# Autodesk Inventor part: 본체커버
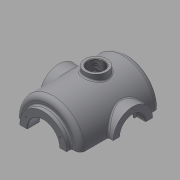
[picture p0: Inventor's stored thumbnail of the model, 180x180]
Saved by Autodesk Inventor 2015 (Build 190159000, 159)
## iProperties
Created: 2016-02
Part Number: 본체커버
Material: 일반
Document SubType Name: Modeling
Designer: mduedu
Density: 1 g/cm^3
Appearance: 기본값
Mass: 438.034 g
Surface Area: 904.884 cm^2
Volume: 438.034 cm^3
Author: mduedu
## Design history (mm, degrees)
sketch "스케치2"
  geometry: L1 (0, 90)-(0, -90); L2 (65, -65.993)-(65, 90); L3 (65, 90)-(0, 90); A1 r 100 centre (0, 10) between (0, -90) and (65, -65.993); 2 further points
  constraints: 6 end point, 2 point on circle, 1 centre point, 1 coincident, 1 horizontal, 1 midpoint, 1 parallel, 1 point on line, 1 vertical
  dimensions: "d3" = 180 distance of L1.start L1.end; "d5" = 130 diameter of L2 L1; "d6" = 100 radius of A1
revolve "회전1" sketch "스케치2" stored, may be unused: angle "d7" = 90 deg
sketch "스케치3"
  geometry: C1 r 47.5 at (0, 0); 1 further point
  constraints: 1 centre point, 1 coincident
  dimensions: "d8" = 95 diameter of C1
extrude "돌출2" join sketch "스케치3" distance "d10" = 10; taper "d11" = 0 deg
sketch "스케치5"
  geometry: L1 (47.5, 100)-(47.5, 90) reference; L2 (47.5, 90)-(65, 90) reference; L3 (65, 90)-(65, -65.993) reference; L4 (-65, -65.993)-(-65, 90) reference; L5 (-65, 90)-(-47.5, 90) reference; L6 (-47.5, 90)-(-47.5, 100) reference; L7 (-47.5, 100)-(47.5, 100) reference; L8 (55, 75)-(55, -61.239); L9 (0, 75)-(55, 75); L10 (0, 75)-(0, -80); A1 r 100 centre (0, 10) between (-65, -65.993) and (0, -90) reference; A2 r 100 centre (0, 10) between (0, -90) and (65, -65.993) reference; A3 r 90 centre (0, 10) between (0, -80) and (55, -61.239); 1 further point
  constraints: 6 end point, 2 point on circle, 1 centre point, 1 parallel, 1 perpendicular, 1 point on line, 1 vertical
  dimensions: "d13" = 10 distance between parallel lines of L3 L8; "d14" = 10 radial gap between concentric circles of A3 A1; "d15" = 15 distance between parallel lines of L9 L2
revolve "회전2" sketch "스케치5" stored, may be unused: angle "d16" = 90 deg
hole "구멍1" diameter "d19" = 65; stored, may be unused: countersink angle "d23" = 90 deg, drill point angle "d25" = 118 deg; dims "d17" = 10, "d18" = 10, "d20" = 6, "d21" = 4, "d22" = 2, "d24" = 8
node "작업 평면1"
sketch "스케치6"
  geometry: L1 (47.5, 100)-(-47.5, 100) reference; C1 r 40 at (0, -7); 1 further point
  constraints: 1 centre point, 1 vertical alignment
  dimensions: "d27" = 80 diameter of C1; "d29" = 107 distance from line of C1.centre L1
extrude "돌출3" join sketch "스케치6" stored distance "d30" = 10; taper "d31" = 0 deg
hole "구멍2" diameter "d34" = 42; stored, may be unused: countersink angle "d38" = 90 deg, drill point angle "d40" = 118 deg; dims "d32" = 10, "d33" = 10, "d35" = 6, "d36" = 52, "d37" = 18, "d39" = 8
sketch "스케치7" dims "d41" = 65
  geometry: C1 r 40 at (0, 0) reference; 3 further points
  constraints: 2 vertical alignment, 1 coincident, 2 other
hole "구멍3" sketch "스케치7" at (0, 32.5) diameter "d43" = 3.242; stored, may be unused: countersink angle "d47" = 90 deg, drill point angle "d49" = 118 deg; dims "d44" = 11, "d45" = 13, "d46" = 18, "d48" = 13
sketch "스케치8" dims "d53" = 80
  geometry: 3 further points
  constraints: 2 vertical alignment, 1 coincident, 2 other
hole "구멍4" sketch "스케치8" at (0, -40) diameter "d56" = 3.242; stored, may be unused: countersink angle "d60" = 90 deg, drill point angle "d62" = 118 deg; dims "d57" = 11, "d58" = 13, "d59" = 18, "d61" = 13
fillet "모깎기1" dims "d66" = 10
fillet "모깎기2" dims "d67" = 3
fillet "모깎기3" dims "d68" = 0.3
chamfer "모따기1" distance "d69" = 1; stored, may be unused: second distance "d70" = 2, angle "d71" = 45 deg
node "작업 평면5"
sketch "스케치10"
  geometry: L1 (-50, 66)-(50, 66); L2 (50, 66)-(50, 50); L3 (50, 50)-(-50, 50); L4 (-50, 50)-(-50, 66); 2 further points
  constraints: 8 end point, 2 horizontal, 2 vertical, 1 midpoint, 1 vertical alignment
  dimensions: "d177" = 50 distance from line of L3 point (0, 0); "d178" = 100 distance of L1.start L1.end; "d179" = 16 distance of L3.end L1.start
extrude "돌출5" join sketch "스케치10" stored distance "d84" = 10; taper "d85" = 0 deg
sketch "스케치21" dims "d180" = 220, "d182" = 130
  geometry: L1 (65, 58)-(-65, 58); L2 (-65, 58)-(-65, -32); L3 (-65, -32)-(65, -32); L4 (65, -32)-(65, 58); L5 (50, 50)-(50, 66) reference; 4 further points
  constraints: 8 end point, 3 horizontal alignment, 3 midpoint, 2 parallel, 1 horizontal, 1 perpendicular, 1 vertical alignment, 4 other
extrude "돌출13" join sketch "스케치21" distance "d183" = 10; taper "d184" = 0 deg
sketch "스케치11"
  geometry: L1 (-65, 80)-(-65, -61.239) reference; L2 (-100, -97)-(-100, -32) reference; L3 (-65, -42.793)-(-100, -63); L4 (-100, -97)-(-110, -97) reference; 1 further point
  constraints: 2 end point, 2 point on line
  dimensions: "d185" = 34 distance from line of L3.end L4; "d186" = 120 deg angle of L2 L3
feature "리브1" sketch "스케치11" dims "d88" = 1, "d89" = 16, "d90" = 0, "d91" = 0, "d92" = 1, "d93" = 1
fillet "모깎기12"
fillet "모깎기13"
fillet "모깎기16" dims "d167" = 3
fillet "모깎기18"
fillet "모깎기17" dims "d168" = 3
fillet "모깎기19" dims "d187" = 3
node "작업 평면6"
sketch "스케치19"
  geometry: L1 (75, -47)-(75, 33) reference; L2 (-75, -47)-(-75, 33) reference; L3 (75, -7)-(-75, -7); C1 r 22.5 at (0, -7); 1 further point
  constraints: 3 midpoint, 2 end point, 1 centre point
  dimensions: "d149" = 45 diameter of C1
extrude "돌출11" join sketch "스케치19" stored distance "d150" = 10; taper "d151" = 0 deg
hole "구멍6" diameter "d154" = 33.376; stored, may be unused: countersink angle "d158" = 90 deg, drill point angle "d160" = 118 deg; dims "d155" = 6, "d156" = 4, "d157" = 2, "d159" = 8, "d190" = 10, "d191" = 10
fillet "모깎기11" dims "d161" = 3
chamfer "모따기3" distance "d164" = 1; stored, may be unused: second distance "d165" = 2, angle "d166" = 45 deg
sketch "스케치22" dims "d189" = 20
  geometry: L1 (-10, -123)-(10, -123); L2 (10, -123)-(10, -103); L3 (10, -103)-(-10, -103); L4 (-10, -103)-(-10, -123); A1 r 65 centre (0, -58) between (-65, -58) and (65, -58) reference; 2 further points
  constraints: 8 end point, 2 parallel, 1 horizontal, 1 horizontal alignment, 1 midpoint, 1 perpendicular, 1 tangent, 1 vertical alignment, 2 other
  dimensions: "d193" = 30 dimension on L1
extrude "돌출14" cut sketch "스케치22" stored distance "d194" = 10; taper "d195" = 0 deg
fillet "모깎기21" dims "d196" = 3
feature "분할1"
node "솔리드2"
pattern_circular "원형 패턴1" dims angle "d51" = 360 deg
mirror "대칭1"
pattern_circular "원형 패턴2" dims angle "d64" = 360 deg
node "절단 모서리 투영1"
other parameters: "d26" = 75, "d136" = 175
